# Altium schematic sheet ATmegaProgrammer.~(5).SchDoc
size A4
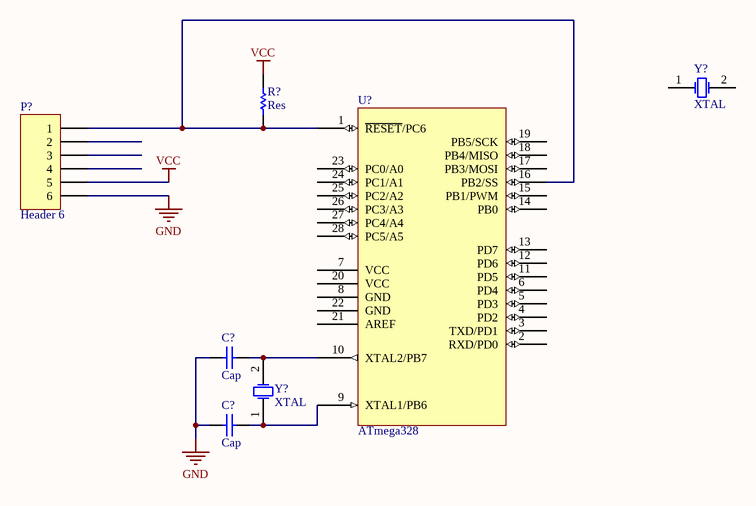
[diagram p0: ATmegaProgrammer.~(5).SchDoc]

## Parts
(Parts that share a designator on the sheet are numbered #1, #2 ... from top to bottom, then left to right.)
C?#1  Cap  [C200]
C?#2  Cap  [C200]
P?  Header 6  [HDR1X6]
R?  Res  [AXIAL-0.3]
U?  ATmega328  [DIP28]
Y?#1  XTAL  [XTAL4-8]
Y?#2  XTAL  [XTAL4-8]

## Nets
GND: C?#1.1 C?#2.1 P?.6
VCC: P?.5 R?.2
NetC?#1_2: C?#1.2 U?.10(XTAL2/PB7) Y?#2.2(OSC2)
NetC?#2_2: C?#2.2 U?.9(XTAL1/PB6) Y?#2.1(OSC1)
NetP?_1: P?.1 R?.1 U?.1(~{RESET}/PC6) U?.16(PB2/SS)

Not connected (* = marked no-connect by the designer): P? 2 3 4; U? 2(RXD/PD0) 3(TXD/PD1) 4(PD2) 5(PD3) 6(PD4) 7(VCC) 8(GND) 11(PD5) 12(PD6) 13(PD7) 14(PB0) 15(PB1/PWM) 17(PB3/MOSI) 18(PB4/MISO) 19(PB5/SCK) 20(VCC) 21(AREF) 22(GND) 23(PC0/A0) 24(PC1/A1) 25(PC2/A2) 26(PC3/A3) 27(PC4/A4) 28(PC5/A5); Y?#1 1(OSC1) 2(OSC2)

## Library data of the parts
C?#1 C?#2 = Cap: Capacitor
P? = Header 6: Header, 6-Pin
R? = Res: Resistor
U? = ATmega328: ATmega¨t¦C³æ´¹¤ù
Y?#1 Y?#2 = XTAL: Crystal Oscillator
